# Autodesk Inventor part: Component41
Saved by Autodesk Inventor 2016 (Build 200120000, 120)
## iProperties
Created: 2016-09
Part Number: Component41
Material: Generic
Document SubType Name: Modeling
Designer: Administrator
Appearance: Generic
Author: Administrator
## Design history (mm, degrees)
feature "Body1"
body "Solid1"
